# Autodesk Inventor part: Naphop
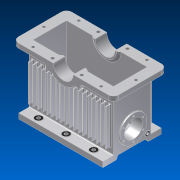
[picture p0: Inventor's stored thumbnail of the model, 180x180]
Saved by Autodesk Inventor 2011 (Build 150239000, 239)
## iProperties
Created: 2011-05
Part Number: Naphop
Document SubType Name: Modeling
Designer: 904Chiaki
Density: 1 g/cm^3
Mass: 10435.2 g
Surface Area: 16982.7 cm^2
Volume: 10435.2 cm^3
Author: 904Chiaki
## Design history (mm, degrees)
sketch "Sketch1"
  geometry: L1 (-32.336, 188.411)-(431.664, 188.411); L2 (431.664, 188.411)-(431.664, -16.589); L3 (431.664, -16.589)-(-32.336, -16.589); L4 (-32.336, -16.589)-(-32.336, 188.411); 1 further point
  constraints: 8 end point, 1 horizontal, 1 vertical
  dimensions: "d0" = 205 distance of L1.end L2.end; "d1" = 464 distance of L1.start L1.end; "d8" = 464 distance of L2.end L3.end; "d42" = 205 distance of L3.end L1.start
extrude "Extrusion1" new body sketch "Sketch1" distance "d2" = 330; taper "d3" = 0 deg
shell "Shell1" dims "d4" = 10
sketch "Sketch2"
  geometry: L1 (464, 330)-(0, 330) reference; C1 r 55 at (232, 330); 1 further point
  constraints: 1 centre point, 1 midpoint
  dimensions: "d5" = 110 diameter of C1
extrude "Extrusion2" cut sketch "Sketch2" stored distance "d6" = 354; taper "d7" = 0 deg
sketch "Sketch3"
  geometry: L1 (-330, 205)-(-330, 0) reference; C1 r 50 at (-90, 102.5); 1 further point
  constraints: 1 centre point
  dimensions: "d11" = 100 diameter of C1; "d98" = 240 distance from line of L1 C1.centre
extrude "Extrusion3" cut sketch "Sketch3" stored distance "d12" = 10; taper "d13" = 0 deg
sketch "Sketch4"
  geometry: C1 r 50 at (240, 92.5) reference; C2 r 77.5 at (240, 92.5); 1 further point
  constraints: 1 centre point, 1 coincident
  dimensions: "d14" = 155 diameter of C2
extrude "Extrusion5" join sketch "Sketch4" distance "d17" = 25; taper "d18" = 0 deg
chamfer "Chamfer1" distance "d19" = 25; stored, may be unused: second distance "d20" = 2, angle "d21" = 30 deg
fillet "Fillet1" dims "d22" = 5
fillet "Fillet2" dims "d23" = 5
sketch "Sketch5"
  geometry: C1 r 50 at (-240, 92.5) reference; C2 r 77.5 at (-240, 92.5); 1 further point
  constraints: 1 centre point, 1 coincident
  dimensions: "d24" = 155 diameter of C2
extrude "Extrusion6" join sketch "Sketch5" distance "d25" = 40; taper "d26" = 0 deg
chamfer "Chamfer2" distance "d27" = 40; stored, may be unused: second distance "d28" = 2, angle "d29" = 20 deg
fillet "Fillet3" dims "d30" = 5
sketch "Sketch6"
  geometry: C1 r 50 at (-90, 102.5) reference; C2 r 74 at (-90, 102.5); 1 further point
  constraints: 1 centre point, 1 coincident
  dimensions: "d31" = 148 diameter of C2
extrude "Extrusion7" join sketch "Sketch6" distance "d32" = 8; taper "d33" = 0 deg
sketch "Sketch7"
  geometry: C1 r 50 at (90, 102.5) reference; C2 r 74 at (90, 102.5); 1 further point
  constraints: 1 centre point, 1 coincident
  dimensions: "d34" = 148 diameter of C2
extrude "Extrusion8" join sketch "Sketch7" distance "d35" = 8; taper "d36" = 0 deg
fillet "Fillet4" dims "d37" = 2
fillet "Fillet5" dims "d38" = 2
sketch "Sketch9"
  geometry: L1 (287, -330)-(464, -330) reference; L2 (0, -330)-(177, -330) reference; L3 (311, -330)-(287, -330); L4 (177, -330)-(153, -330); A1 r 55 centre (232, -330) between (287, -330) and (177, -330) reference; A2 r 79 centre (232, -330) between (311, -330) and (153, -330); A3 r 55 centre (232, -330) between (287, -330) and (177, -330); 1 further point
  constraints: 4 end point, 4 point on circle, 2 centre point, 2 coincident, 2 point on line
  dimensions: "d46" = 158 diameter of A2
extrude "Extrusion9" join sketch "Sketch9" distance "d47" = 45; taper "d48" = 0 deg
sketch "Sketch10"
  geometry: L1 (0, 320)-(167, 320) reference; L2 (277, 320)-(444, 320) reference; L3 (301, 320)-(277, 320); L4 (167, 320)-(143, 320); A1 r 55 centre (222, 320) between (167, 320) and (277, 320) reference; A2 r 79 centre (222, 320) between (143, 320) and (301, 320); A3 r 55 centre (222, 320) between (167, 320) and (277, 320); 1 further point
  constraints: 4 end point, 4 point on circle, 2 centre point, 2 coincident, 2 point on line
  dimensions: "d49" = 158 diameter of A2
extrude "Extrusion10" join sketch "Sketch10" distance "d50" = 10; taper "d51" = 0 deg
chamfer "Chamfer3" distance "d52" = 10; stored, may be unused: second distance "d53" = 15, angle "d54" = 30 deg
workplane "Work Plane1"
mirror "Mirror1"
chamfer "Chamfer4" distance "d56" = 10; stored, may be unused: second distance "d57" = 15, angle "d58" = 30 deg
sketch "Sketch11"
  geometry: L1 (254.664, 3.411)-(254.664, -61.589) reference; L2 (431.664, 188.411)-(431.664, -16.589) reference; L3 (254.664, 233.411)-(254.664, 168.411) reference; L4 (278.664, 178.411)-(421.664, 178.411) reference; L5 (421.664, 178.411)-(421.664, -6.589) reference; L6 (421.664, -6.589)-(278.664, -6.589) reference; L7 (476.664, 233.411)-(476.664, -61.589); L8 (-77.336, -61.589)-(-77.336, 233.411); L9 (-32.336, 188.411)-(120.664, 188.411) reference; L10 (-32.336, -16.589)-(-32.336, 188.411) reference; L11 (120.664, -16.589)-(-32.336, -16.589) reference; L12 (120.664, 188.411)-(120.664, 233.411) reference; L13 (144.664, 168.411)-(144.664, 233.411) reference; L14 (144.664, -61.589)-(144.664, 3.411) reference; L15 (120.664, -6.589)-(135.664, 3.411) reference; L16 (120.664, -6.589)-(-22.336, -6.589) reference; L17 (-22.336, -6.589)-(-22.336, 178.411) reference; L18 (-22.336, 178.411)-(120.664, 178.411) reference; L19 (135.664, 168.411)-(120.664, 178.411) reference; L20 (135.664, 168.411)-(144.664, 168.411) reference; L21 (144.664, 168.411)-(144.664, 233.411) reference; L22 (144.664, 233.411)-(120.664, 233.411) reference; L23 (120.664, 188.411)-(120.664, 233.411) reference; L24 (-32.336, 188.411)-(120.664, 188.411) reference; L25 (-32.336, -16.589)-(-32.336, 188.411) reference; L26 (120.664, -16.589)-(-32.336, -16.589) reference; L27 (120.664, -16.589)-(120.664, -61.589) reference; L28 (144.664, -61.589)-(120.664, -61.589) reference; L29 (144.664, -61.589)-(144.664, 3.411) reference; L30 (135.664, 3.411)-(144.664, 3.411) reference; L31 (-77.336, 233.411)-(144.664, 233.411); L32 (254.664, 233.411)-(476.664, 233.411); L33 (476.664, -61.589)-(254.664, -61.589); L34 (144.664, -61.589)-(-77.336, -61.589); L35 (278.664, 178.411)-(254.664, 178.411); L36 (144.664, 178.411)-(120.664, 178.411); L37 (278.664, -6.589)-(254.664, -6.589); L38 (144.664, -6.589)-(120.664, -6.589); 1 further point
  constraints: 24 end point, 4 point on line
  dimensions: "d60" = 45 distance between parallel lines of L2 L7; "d62" = 45 distance between parallel lines of L8 L10
extrude "Extrusion11" join sketch "Sketch11" distance "d63" = 25; taper "d64" = 0 deg
sketch "Sketch12"
  geometry: L1 (0, 0)-(0, 320) reference; L2 (0, 0)-(444, 0) reference; L3 (444, 0)-(0, 3.875); 1 further point
  constraints: 2 end point, 1 point on line
  dimensions: "d66" = 0.5 deg angle of L2 L3
extrude "Extrusion12" join sketch "Sketch12" stored distance "d67" = 25; taper "d68" = 0 deg
sketch "Sketch13"
  geometry: L1 (-222, -316.125)-(222, -320) reference; L2 (222, -320)-(202, -320); L3 (202, -320)-(202, -319.825); 1 further point
  constraints: 4 end point, 1 point on line
  dimensions: "d69" = 20 distance of L1.end L2.end
extrude "Extrusion13" cut sketch "Sketch13" distance "d70" = 20; taper "d71" = 0 deg
workplane "Work Plane2"
sketch "Sketch14"
  geometry: L1 (-431.664, 246.411)-(32.336, 246.411); L2 (32.336, -74.589)-(-431.664, -74.589); L3 (32.336, 9.911)-(32.336, 161.911) reference; L4 (-431.664, 161.911)-(-431.664, 9.911) reference; L5 (-274.604, 188.411)-(-431.664, 188.411) reference; L6 (-431.664, -16.589)-(-274.604, -16.589) reference; L7 (-274.604, 188.411)-(-124.724, 188.411) reference; L8 (32.336, 188.411)-(-124.724, 188.411) reference; L9 (-124.724, -16.589)-(32.336, -16.589) reference; L10 (-124.724, -16.589)-(-274.604, -16.589) reference; L11 (32.336, 188.411)-(-431.664, 188.411); L12 (-431.664, -16.589)-(32.336, -16.589); L13 (32.336, 246.411)-(32.336, 188.411); L14 (32.336, -16.589)-(32.336, -74.589); L15 (-431.664, -74.589)-(-431.664, -16.589); L16 (-431.664, 188.411)-(-431.664, 246.411); 1 further point
  constraints: 17 end point
  dimensions: "d75" = 58 distance between parallel lines of L5 L1; "d76" = 58 distance between parallel lines of L2 L6
extrude "Extrusion14" join sketch "Sketch14" distance "d77" = 29; taper "d78" = 0 deg
sketch "Sketch15"
  geometry: L1 (0, 0)-(464, 0) reference; L2 (0, 0)-(0, -19) reference; L3 (0, -19)-(464, -19) reference; L4 (464, 0)-(464, -19) reference; 1 further point
extrude "Extrusion15" join sketch "Sketch15" distance "d79" = 20; taper "d80" = 0 deg
sketch "Sketch16"
  geometry: L1 (464, 0)-(0, 0) reference; L2 (464, 0)-(464, 19) reference; L3 (464, 19)-(0, 19) reference; L4 (0, 0)-(0, 19) reference; 1 further point
extrude "Extrusion16" join sketch "Sketch16" distance "d81" = 20; taper "d82" = 0 deg
fillet "Fillet6" dims "d83" = 10
sketch "Sketch17"
  geometry: C1 r 19 at (351.664, 217.411); C2 r 19 at (199.664, 217.411); C3 r 19 at (47.664, 217.411); 1 further point
  constraints: 3 centre point
  dimensions: "d87" = 38 diameter of C1; "d88" = 38 diameter of C2; "d89" = 38 diameter of C3
extrude "Extrusion17" join sketch "Sketch17" distance "d90" = 2; taper "d91" = 0 deg
fillet "Fillet7" dims "d92" = 2
sketch "Sketch18"
  geometry: L1 (-384, -39)-(80, -39) reference; L2 (-384, 29)-(-384, -39) reference; L3 (80, 29)-(-384, 29) reference; L4 (80, -39)-(80, 29) reference; C1 r 19 at (0, 0) reference; C2 r 19 at (-304, 0) reference; C3 r 21 at (-304, 0) reference; C4 r 19 at (-152, 0) reference; C5 r 21 at (-152, 0) reference; C6 r 9 at (-304, 0); C7 r 9 at (-152, 0); C8 r 9 at (0, 0); 1 further point
  constraints: 3 centre point, 3 coincident
  dimensions: "d93" = 18 diameter of C6; "d94" = 18 diameter of C7; "d95" = 18 diameter of C8
extrude "Extrusion18" cut sketch "Sketch18" stored distance "d96" = 2; taper "d97" = 0 deg
mirror "Mirror2"
fillet "Fillet8" dims "d99" = 30
sketch "Sketch19"
  geometry: L1 (232, -25)-(74.94, -25) reference; L2 (-74.94, -25)-(-232, -25) reference; L3 (-96.164, -50)-(-61.164, -50); L4 (61.164, -50)-(96.164, -50); L5 (96.164, -50)-(96.164, -25); L6 (-96.164, -50)-(-96.164, -25); A1 r 79 centre (0, 0) between (-74.94, -25) and (74.94, -25) reference; 1 further point
  constraints: 8 end point, 2 point on circle, 2 point on line
  dimensions: "d101" = 35 distance from line of L4.start L5; "d102" = 35 distance from line of L3.end L6
extrude "Extrusion19" join sketch "Sketch19" stored distance "d103" = 10; taper "d104" = 0 deg
mirror "Mirror3"
fillet "Fillet9" dims "d105" = 10
fillet "Fillet10" dims "d106" = 5
fillet "Fillet11" dims "d107" = 2
workplane "Work Plane3"
  workaxis "Work Axis1"
sketch "Sketch20"
  geometry: L1 (45, 79)-(0, 139); L2 (45, 79)-(45, 68.645); 1 further point
  constraints: 4 end point
  dimensions: "d109" = 60 vertical distance of L1.end L1.start
feature "Rib1" sketch "Sketch20" dims "d110" = 1, "d111" = 10, "d112" = 0
mirror "Mirror4"
fillet "Fillet12" dims "d113" = 2
fillet "Fillet13" dims "d114" = 5
fillet "Fillet14" dims "d115" = 5
sketch "Sketch21"
  geometry: L1 (0, -68)-(-320, -68) reference; L2 (-3.875, -134.674)-(-3.875, -68) reference; C1 r 8 at (-11.875, -76); 1 further point
  constraints: 1 centre point
  dimensions: "d118" = 16 diameter of C1; "d119" = 8 distance from line of L2 C1.centre; "d120" = 8 distance from line of L1 C1.centre
extrude "Extrusion20" cut sketch "Sketch21" stored distance "d121" = 10; taper "d122" = 0 deg
sketch "Sketch22"
  geometry: C1 r 8 at (-11.875, -76) reference; C2 r 12.5 at (-11.875, -76); 1 further point
  constraints: 1 centre point, 1 coincident
  dimensions: "d123" = 25 diameter of C2
extrude "Extrusion21" join sketch "Sketch22" distance "d124" = 2; taper "d125" = 0 deg
fillet "Fillet16" dims "d126" = 2
thread "Thread1" dims "d127" = 10, "d128" = 0
node "Hole2"
node "Hole4"
node "Hole6"
node "Hole8"
node "Hole10"
sketch "Sketch29"
  geometry: L1 (0, 288)-(464, 288) reference; L2 (16.78, 258)-(21.78, 258); L3 (16.78, 258)-(16.78, 58); L4 (21.78, 258)-(21.78, 58); L5 (16.78, 58)-(21.78, 58); 1 further point
  constraints: 8 end point, 1 parallel
  dimensions: "d196" = 30 distance between parallel lines of L1 L2; "d197" = 200 distance of L2.start L3.end; "d198" = 5 distance between parallel lines of L3 L4
extrude "Extrusion22" join sketch "Sketch29" distance "d199" = 25; taper "d200" = 0 deg
fillet "Fillet17" dims "d204" = 5
fillet "Fillet18" dims "d205" = 5
fillet "Fillet19" dims "d206" = 5
fillet "Fillet20" dims "d207" = 5
fillet "Fillet21" dims "d208" = 2
mirror "Mirror5"
fillet "Fillet22" dims "d209" = 2
fillet "Fillet23" dims "d210" = 5
fillet "Fillet24" dims "d211" = 5
fillet "Fillet25" dims "d212" = 5
fillet "Fillet26" dims "d213" = 5
body "Solid1"
pattern_linear "Rectangular Pattern1" dims "d203" = 25
node "Projected Loop1"
node "Projected Loop2"
node "Projected Loop3"
node "Projected Loop4"
sketch "Sketch23"
  geometry: 4 further points
hole "Hole1" sketch "Sketch23" diameter "d129" = 17.5; stored, may be unused: countersink angle "d133" = 90 deg, drill point angle "d135" = 0 deg; dims "d130" = 6, "d131" = 4, "d132" = 2, "d134" = 8
sketch "Sketch24"
  geometry: 6 further points
hole "Hole3" sketch "Sketch24" diameter "d136" = 15.5; stored, may be unused: countersink angle "d140" = 90 deg, drill point angle "d142" = 0 deg; dims "d137" = 6, "d138" = 4, "d139" = 2, "d141" = 8
sketch "Sketch25"
  geometry: 1 further point
hole "Hole5" sketch "Sketch25" diameter "d143" = 4; stored, may be unused: countersink angle "d147" = 90 deg, drill point angle "d149" = 0 deg; dims "d144" = 6, "d145" = 4, "d146" = 2, "d148" = 8
sketch "Sketch26"
  geometry: 6 further points
hole "Hole7" sketch "Sketch26" diameter "d150" = 8.376; stored, may be unused: countersink angle "d154" = 90 deg, drill point angle "d156" = 120 deg; dims "d151" = 19, "d152" = 4, "d153" = 2, "d155" = 24
sketch "Sketch27"
  geometry: 6 further points
hole "Hole9" sketch "Sketch27" diameter "d157" = 8.376; stored, may be unused: countersink angle "d161" = 90 deg, drill point angle "d163" = 120 deg; dims "d158" = 19, "d159" = 4, "d160" = 2, "d162" = 24
other parameters: "d55" = -102.5, "d59" = 45, "d61" = 45, "d73" = 0, "d74" = 0, "d100" = 25, "d108" = 0
